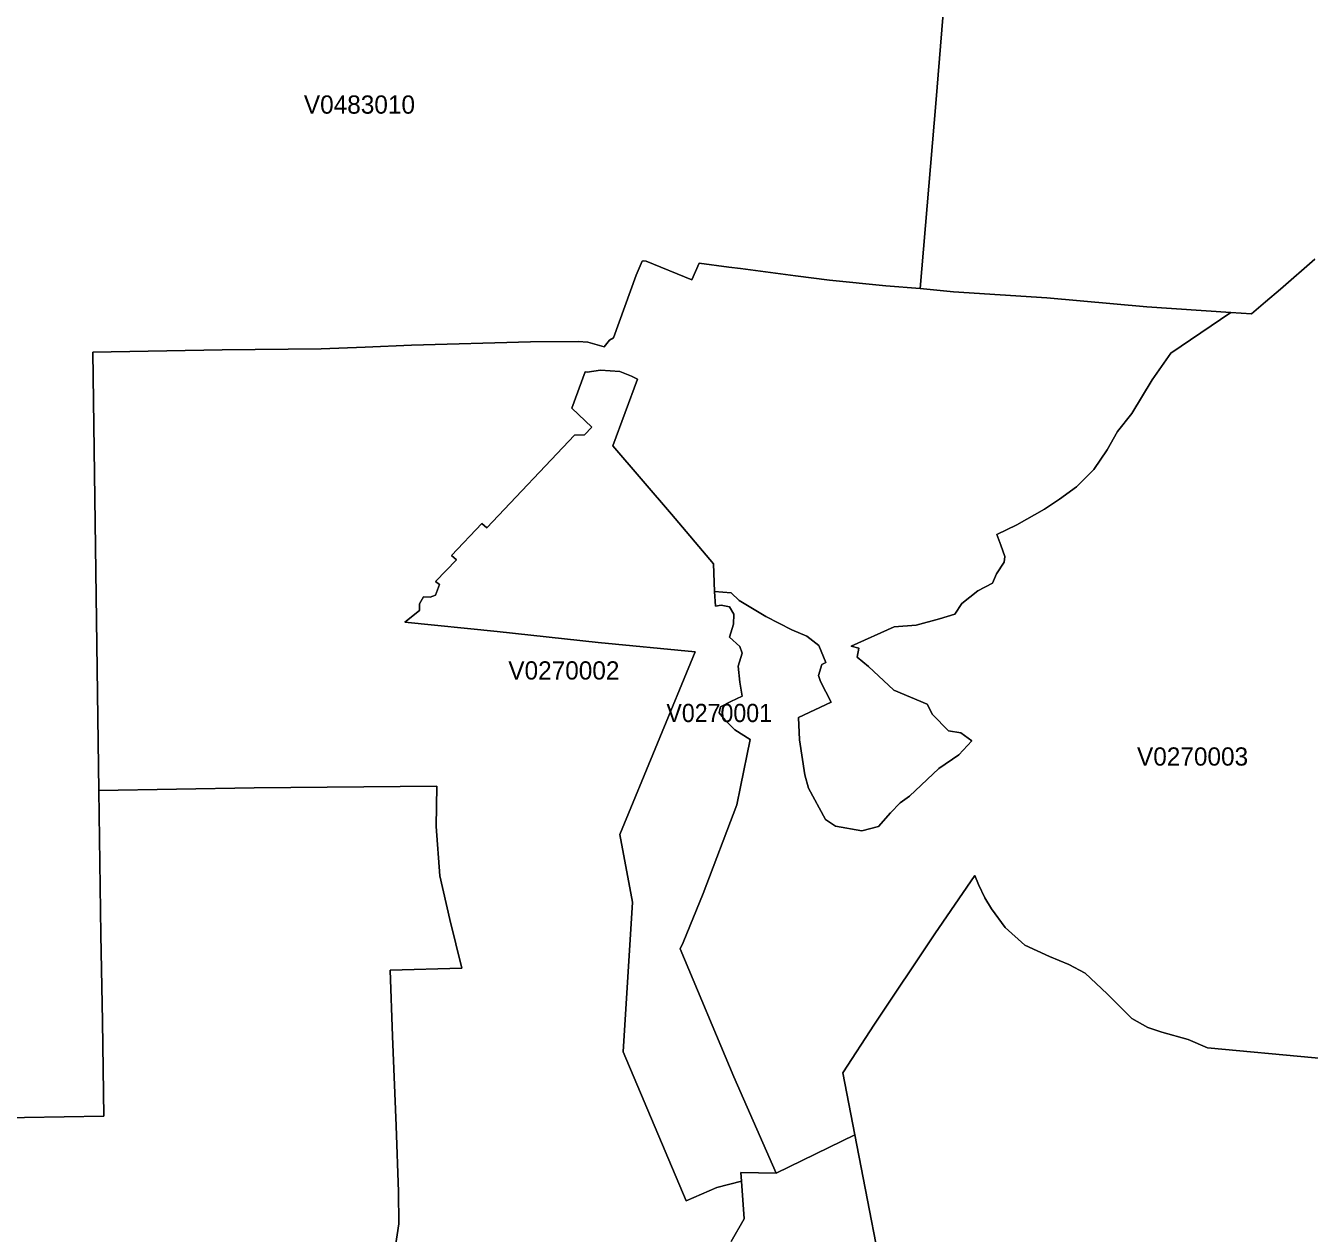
# Model space of a CAD drawing. Extents: x 369010 to 735936, y 6377141 to 6616555.
# Drawn here: x 406662 to 413706, y 6477197 to 6483823 of the extents above; entities that cross this region are included whole.
import ezdxf
from ezdxf.enums import TextEntityAlignment as Align

# ---------------------------------------------------------------- set-up
doc = ezdxf.new("R2010")
doc.units = 0
doc.header["$LTSCALE"] = 40
doc.layers.add('3', color=7, linetype='Continuous', lineweight=13)
doc.layers.add('4', color=7, linetype='Continuous')

msp = doc.modelspace()

# ---------------------------------------------------------------- linework, layer by layer
at = {"layer": '3'}
for points in [[(407074.47, 6478836.74), (407063.38, 6479626.52), (407029.95, 6482031.13), (407739.63, 6482044.37), (408283.97, 6482049.67), (408525.78, 6482058.94), (408779.49, 6482069.36), (409431.58, 6482089.06), (409694.07, 6482090.88), (409747.86, 6482086.41), (409836.73, 6482061.42), (409866.19, 6482098.16), (409888.54, 6482110.57), (410012, 6482454.99), (410044.77, 6482530.29), (410052.55, 6482532.61), (410067.11, 6482531.12), (410317.52, 6482429.5), (410358.9, 6482519.2), (410520.43, 6482498.85), (410584.48, 6482490.9), (410887.52, 6482450.19), (411073.05, 6482426.19), (411382.37, 6482395.41), (411571.05, 6482381.5), (411655.95, 6483395.71), (411714.87, 6484116.65)], [(411714.87, 6484116.65), (411655.95, 6483395.71), (411571.05, 6482381.5), (411754.26, 6482363.13), (412265.01, 6482329.21), (412815.14, 6482280.88), (413275.57, 6482250.26), (413388.78, 6482242.81), (413465.57, 6482307.36), (413548.49, 6482378.19), (413737.33, 6482542.37)], [(411192.71, 6480418.63), (411427.72, 6480524.22), (411549.7, 6480534.15), (411676.81, 6480568.24), (411760.22, 6480593.23), (411800.27, 6480653.15), (411886.33, 6480721.66), (411968.09, 6480764.36), (411989.94, 6480816), (412032.14, 6480878.56), (412035.45, 6480910.17), (412013.61, 6480973.23), (411991.26, 6481031.16), (412100.66, 6481084.45), (412252.93, 6481170.18), (412335.84, 6481224.8), (412429.35, 6481293.32), (412523.36, 6481388.65), (412597.5, 6481496.22), (412654.44, 6481596.35), (412731.73, 6481695.32), (412844.44, 6481879.53), (412945.89, 6482026.33), (413275.57, 6482250.26), (412815.14, 6482280.88), (412265.01, 6482329.21), (411754.26, 6482363.13), (411571.05, 6482381.5), (411382.37, 6482395.41), (411073.05, 6482426.19), (410887.52, 6482450.19), (410584.48, 6482490.9), (410520.43, 6482498.85), (410358.9, 6482519.2), (410317.52, 6482429.5), (410067.11, 6482531.12), (410052.55, 6482532.61), (410044.77, 6482530.29), (410012, 6482454.99), (409888.54, 6482110.57), (409866.19, 6482098.16), (409836.73, 6482061.42), (409747.86, 6482086.41), (409694.07, 6482090.88), (409431.58, 6482089.06), (408779.49, 6482069.36), (408525.78, 6482058.94), (408283.97, 6482049.67), (407739.63, 6482044.37), (407029.95, 6482031.13), (407063.38, 6479626.52)], [(413737.33, 6482542.37), (413548.49, 6482378.19), (413465.57, 6482307.36), (413388.78, 6482242.81), (413275.57, 6482250.26)], [(413275.57, 6482250.26), (412945.89, 6482026.33), (412844.44, 6481879.53), (412731.73, 6481695.32), (412654.44, 6481596.35), (412597.5, 6481496.22), (412523.36, 6481388.65), (412429.35, 6481293.32), (412335.84, 6481224.8), (412252.93, 6481170.18), (412100.66, 6481084.45), (411991.26, 6481031.16), (412013.61, 6480973.23), (412035.45, 6480910.17), (412032.14, 6480878.56), (411989.94, 6480816), (411968.09, 6480764.36), (411886.33, 6480721.66), (411800.27, 6480653.15), (411760.22, 6480593.23), (411676.81, 6480568.24), (411549.7, 6480534.15), (411427.72, 6480524.22), (411192.71, 6480418.63), (411234.25, 6480406.71), (411224.98, 6480358.05), (411286.88, 6480307.24), (411427.06, 6480176.83), (411609.11, 6480099.7), (411638.74, 6480043.76), (411725.63, 6479954.72), (411793.49, 6479943.46), (411853.4, 6479899.28), (411783.72, 6479821.49), (411673.66, 6479746.85), (411512.46, 6479595.41), (411460.99, 6479559.16), (411408.03, 6479504.22), (411342.16, 6479429.91), (411250.63, 6479405.08), (411105.82, 6479431.06), (411050.54, 6479467.31), (410957.53, 6479639.93), (410937.83, 6479712.42), (410907.87, 6479904.07), (410902.58, 6480027.87), (411081.65, 6480111.12), (411023.23, 6480224.66), (411011.98, 6480258.25), (411031.84, 6480317.5), (411052.19, 6480328.1), (411014.46, 6480421.61), (410948.59, 6480473.08), (410866.66, 6480507.67), (410723.83, 6480581.81), (410576.87, 6480669.7), (410534, 6480711.07), (410442.31, 6480719.02), (410446.95, 6480638.75), (410477.9, 6480642.72), (410524.73, 6480634.11), (410548.9, 6480594.39), (410545.59, 6480539.78), (410523.74, 6480467.45), (410581.67, 6480416.64), (410594.24, 6480379.9), (410572.89, 6480309.39), (410581.5, 6480221.18), (410593.25, 6480144.72), (410531.85, 6480115.75), (410475.91, 6480086.13), (410467.96, 6480052.04), (410500.9, 6480012.48), (410553.36, 6479960.18), (410637.11, 6479906.89), (410585.64, 6479646.05), (410564.29, 6479547.91), (410380.08, 6479061.83), (410269.86, 6478792.22), (410253.97, 6478757.3), (410548.9, 6478056.06), (410780.93, 6477527.27), (411211.57, 6477737.13), (411146.86, 6478078.07), (411320.81, 6478344.03), (411650.82, 6478840.05), (411870.45, 6479159.8), (411891.46, 6479111.15), (411925.72, 6479037.33), (411961.31, 6478977.75), (412037.77, 6478874.97), (412145.02, 6478778.15), (412281.23, 6478715.92), (412386.82, 6478672.06), (412476.69, 6478623.57), (412597.01, 6478510.37), (412732.06, 6478375.31), (412819.94, 6478326.99), (412896.07, 6478300.18), (413040.56, 6478260.29)], [(410534.17, 6477151.41), (410604.51, 6477276.37), (410590.11, 6477482.75), (410590.11, 6477482.75), (410454.72, 6477447.33), (410286.9, 6477375.84), (409940.34, 6478192.6), (409992.8, 6479013.99), (409921.97, 6479384.39), (410336.39, 6480386.68), (409802.97, 6480439.15), (409250.02, 6480499.56), (408742.92, 6480551.03), (408824.01, 6480614.91), (408823.19, 6480650), (408845.69, 6480688.89), (408881.11, 6480687.57), (408911.57, 6480697.5), (408932.58, 6480756.09), (408911.57, 6480773.14), (409026.92, 6480891.8), (408998.62, 6480916.79), (409165.12, 6481091.24), (409193.42, 6481068.23), (409673.38, 6481576.66), (409729.49, 6481578.64), (409769.54, 6481620.85), (409660.14, 6481724.45), (409731.64, 6481923.72), (409742.73, 6481921.73), (409817.2, 6481932.33), (409922.79, 6481924.88), (409986.18, 6481899.89), (410019.78, 6481884.33), (409885.06, 6481517.9), (410205.97, 6481143.2), (410436.52, 6480870.62), (410442.31, 6480719.02), (410534, 6480711.07), (410576.87, 6480669.7), (410723.83, 6480581.81), (410866.66, 6480507.67), (410948.59, 6480473.08), (411014.46, 6480421.61), (411052.19, 6480328.1), (411031.84, 6480317.5), (411011.98, 6480258.25), (411023.23, 6480224.66), (411081.65, 6480111.12), (410902.58, 6480027.87), (410907.87, 6479904.07), (410937.83, 6479712.42), (410957.53, 6479639.93), (411050.54, 6479467.31), (411105.82, 6479431.06), (411250.63, 6479405.08), (411342.16, 6479429.91), (411408.03, 6479504.22), (411460.99, 6479559.16), (411512.46, 6479595.41), (411673.66, 6479746.85), (411783.72, 6479821.49), (411853.4, 6479899.28), (411793.49, 6479943.46), (411725.63, 6479954.72), (411638.74, 6480043.76), (411609.11, 6480099.7), (411427.06, 6480176.83), (411286.88, 6480307.24), (411224.98, 6480358.05), (411234.25, 6480406.71), (411192.71, 6480418.63)], [(408917.69, 6479650.69), (407916.22, 6479641.75), (407063.38, 6479626.52), (407063.38, 6479626.52), (407074.47, 6478836.74), (407083.9, 6478359.59), (407090.86, 6477838.92), (405347.27, 6477810.78), (404955.52, 6477804.49), (403702.16, 6477779.5), (403510.01, 6477583.05), (403451.42, 6477523.13), (403243.38, 6477358.46), (403039.15, 6477204.87), (402555.38, 6477292.42), (402544.46, 6477282.16), (402552.57, 6477174.91)], [(407063.38, 6479626.52), (407063.38, 6479626.52), (407916.22, 6479641.75), (408917.69, 6479650.69), (408914.38, 6479429.74), (408935.07, 6479158.81), (408989.35, 6478918.66), (409055.88, 6478651.21), (408662.65, 6478640.29), (408675.06, 6478279.49), (408695.25, 6477786.12), (408708.16, 6477424.99), (408710.31, 6477249.72), (408691.94, 6477128.24)], [(408691.94, 6477128.24), (408710.31, 6477249.72), (408708.16, 6477424.99), (408695.25, 6477786.12), (408675.06, 6478279.49), (408662.65, 6478640.29), (409055.88, 6478651.21), (408989.35, 6478918.66), (408935.07, 6479158.81), (408914.38, 6479429.74), (408917.69, 6479650.69)], [(414328.51, 6478104.05), (413147.81, 6478213.95), (413040.56, 6478260.29), (412896.07, 6478300.18), (412819.94, 6478326.99), (412732.06, 6478375.31), (412597.01, 6478510.37), (412476.69, 6478623.57), (412386.82, 6478672.06), (412281.23, 6478715.92), (412145.02, 6478778.15), (412037.77, 6478874.97), (411961.31, 6478977.75), (411925.72, 6479037.33), (411891.46, 6479111.15), (411870.45, 6479159.8), (411650.82, 6478840.05), (411320.81, 6478344.03), (411146.86, 6478078.07), (411211.57, 6477737.13)], [(405347.27, 6477810.78), (407090.86, 6477838.92), (407083.9, 6478359.59), (407074.47, 6478836.74)], [(413040.56, 6478260.29), (413147.81, 6478213.95), (414328.51, 6478104.05)], [(411407.86, 6476726.73), (411211.57, 6477737.13), (410780.93, 6477527.27), (410586.8, 6477529.75), (410590.11, 6477482.75), (410604.51, 6477276.37), (410534.17, 6477151.41)], [(411211.57, 6477737.13), (411407.86, 6476726.73)]]:
    msp.add_lwpolyline(points, dxfattribs=at)
msp.add_lwpolyline([(410590.11, 6477482.75), (410586.8, 6477529.75), (410780.93, 6477527.27), (410548.9, 6478056.06), (410253.97, 6478757.3), (410269.86, 6478792.22), (410380.08, 6479061.83), (410564.29, 6479547.91), (410585.64, 6479646.05), (410637.11, 6479906.89), (410553.36, 6479960.18), (410500.9, 6480012.48), (410467.96, 6480052.04), (410475.91, 6480086.13), (410531.85, 6480115.75), (410593.25, 6480144.72), (410581.5, 6480221.18), (410572.89, 6480309.39), (410594.24, 6480379.9), (410581.67, 6480416.64), (410523.74, 6480467.45), (410545.59, 6480539.78), (410548.9, 6480594.39), (410524.73, 6480634.11), (410477.9, 6480642.72), (410446.95, 6480638.75), (410442.31, 6480719.02), (410436.52, 6480870.62), (410205.97, 6481143.2), (409885.06, 6481517.9), (410019.78, 6481884.33), (409986.18, 6481899.89), (409922.79, 6481924.88), (409817.2, 6481932.33), (409742.73, 6481921.73), (409731.64, 6481923.72), (409660.14, 6481724.45), (409769.54, 6481620.85), (409729.49, 6481578.64), (409673.38, 6481576.66), (409193.42, 6481068.23), (409165.12, 6481091.24), (408998.62, 6480916.79), (409026.92, 6480891.8), (408911.57, 6480773.14), (408932.58, 6480756.09), (408911.57, 6480697.5), (408881.11, 6480687.57), (408845.69, 6480688.89), (408823.19, 6480650), (408824.01, 6480614.91), (408742.92, 6480551.03), (409250.02, 6480499.56), (409802.97, 6480439.15), (410336.39, 6480386.68), (409921.97, 6479384.39), (409992.8, 6479013.99), (409940.34, 6478192.6), (410286.9, 6477375.84), (410454.72, 6477447.33), (410590.11, 6477482.75)], close=True, dxfattribs=at)

# ---------------------------------------------------------------- texts
at = {"layer": '4'}
for s, p in [('V0483010', (408493.73, 6483340.46)), ('V0270002', (409615.57, 6480235.44)), ('V0270003', (413065.54, 6479763.18))]:
    msp.add_text(s, height=100, dxfattribs=at).set_placement(p, align=Align.CENTER)
at = {"layer": '4', "width": 0.95}
msp.add_text('V0270001', height=100, dxfattribs=at).set_placement((410467.97, 6480002.03), align=Align.CENTER)

doc.saveas('drawing.dxf')
